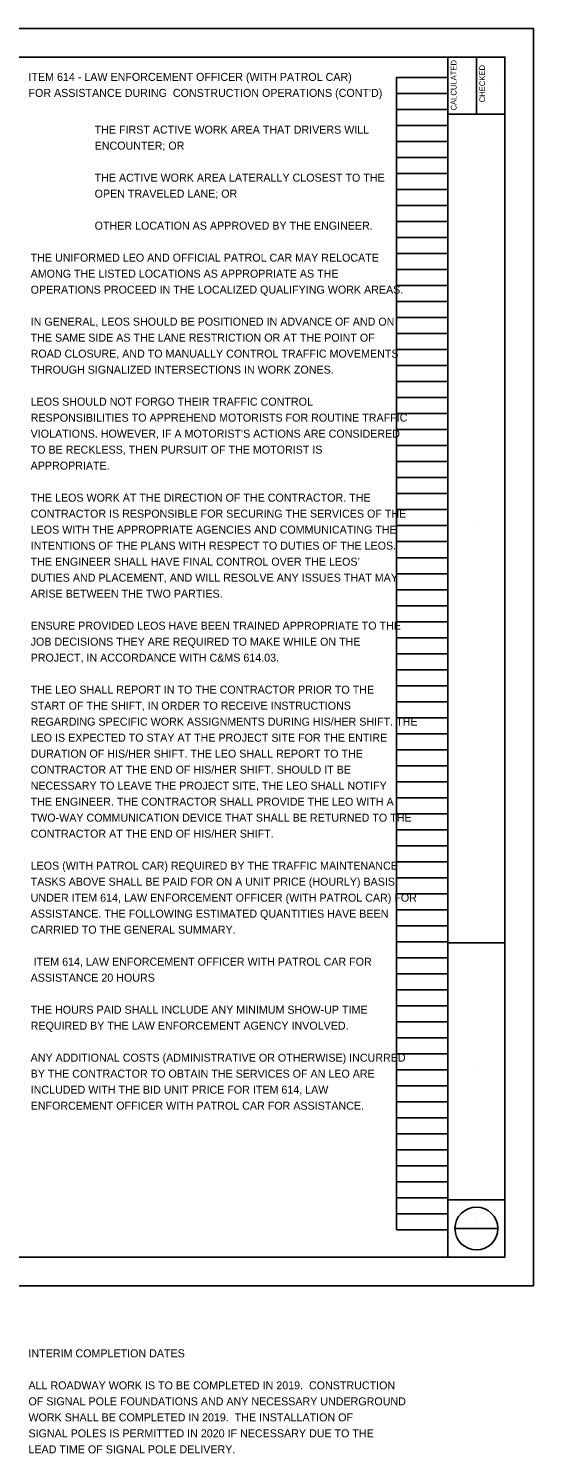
# Model space of a CAD drawing. Extents: x -10.9 to 54.4, y -2.9 to 34.3.
# Drawn here: x 25.16 to 34, y -2.94 to 22 of the extents above; entities that cross this region are included whole.
import ezdxf

# ---------------------------------------------------------------- set-up
doc = ezdxf.new("R2010")
doc.units = 0
for name, color, linetype in [('MT_P_Work_Area', 7, 'Continuous'), ('SH_Cut_Line', 7, 'Continuous'), ('SH_Data', 7, 'Continuous'), ('SH_Text', 7, 'Continuous')]:
    doc.layers.add(name, color=color, linetype=linetype)

msp = doc.modelspace()

# ---------------------------------------------------------------- linework, layer by layer
at = {"layer": 'MT_P_Work_Area'}
for p, q in [((32.5, 0.5), (32.5, 21.5)), ((33, 21.5), (33, 20.5)), ((32.5, 20.5), (33.5, 20.5)), ((32.5, 6), (33.5, 6)), ((32.5, 1.5), (33.5, 1.5))]:
    msp.add_line(p, q, dxfattribs=at)
msp.add_lwpolyline([(2, 21.5), (33.5, 21.5), (33.5, 0.5), (2, 0.5)], close=True, dxfattribs=at)
at = {"layer": 'SH_Cut_Line'}
msp.add_lwpolyline([(0, 0), (34, 0), (34, 22), (0, 22)], close=True, dxfattribs=at)
at = {"layer": 'SH_Data'}
for p, q in [((31.6, 0.98), (31.6, 21.14)), ((31.6, 21.14), (32.5, 21.14)), ((32.5, 0.98), (32.5, 21.14)), ((32.92, 21.004), (32.92, 21.004)), ((33.42, 21.004), (33.42, 21.004)), ((31.6, 20.86), (32.5, 20.86)), ((31.6, 20.58), (32.5, 20.58)), ((31.6, 20.3), (32.5, 20.3)), ((31.6, 20.02), (32.5, 20.02)), ((31.6, 19.74), (32.5, 19.74)), ((31.6, 19.46), (32.5, 19.46)), ((31.6, 19.18), (32.5, 19.18)), ((31.6, 18.9), (32.5, 18.9)), ((31.6, 18.62), (32.5, 18.62)), ((31.6, 18.34), (32.5, 18.34)), ((31.6, 18.06), (32.5, 18.06)), ((31.6, 17.78), (32.5, 17.78)), ((31.6, 17.5), (32.5, 17.5)), ((31.6, 17.22), (32.5, 17.22)), ((31.6, 16.94), (32.5, 16.94)), ((31.6, 16.66), (32.5, 16.66)), ((31.6, 16.38), (32.5, 16.38)), ((31.6, 16.1), (32.5, 16.1)), ((31.6, 15.82), (32.5, 15.82)), ((31.6, 15.54), (32.5, 15.54)), ((31.6, 15.26), (32.5, 15.26)), ((31.6, 14.98), (32.5, 14.98)), ((31.6, 14.7), (32.5, 14.7)), ((31.6, 14.42), (32.5, 14.42)), ((31.6, 14.14), (32.5, 14.14)), ((31.6, 13.86), (32.5, 13.86)), ((31.6, 13.58), (32.5, 13.58)), ((31.6, 13.3), (32.5, 13.3)), ((33, 13.292), (33, 13.292)), ((31.6, 13.02), (32.5, 13.02)), ((31.6, 12.74), (32.5, 12.74)), ((31.6, 12.46), (32.5, 12.46)), ((31.6, 12.18), (32.5, 12.18)), ((31.6, 11.9), (32.5, 11.9)), ((31.6, 11.62), (32.5, 11.62)), ((31.6, 11.34), (32.5, 11.34)), ((31.6, 11.06), (32.5, 11.06)), ((31.6, 10.78), (32.5, 10.78)), ((31.6, 10.5), (32.5, 10.5)), ((31.6, 10.22), (32.5, 10.22)), ((31.6, 9.94), (32.5, 9.94)), ((31.6, 9.66), (32.5, 9.66)), ((31.6, 9.38), (32.5, 9.38)), ((31.6, 9.1), (32.5, 9.1)), ((31.6, 8.82), (32.5, 8.82)), ((31.6, 8.54), (32.5, 8.54)), ((31.6, 8.26), (32.5, 8.26)), ((31.6, 7.98), (32.5, 7.98)), ((31.6, 7.7), (32.5, 7.7)), ((31.6, 7.42), (32.5, 7.42)), ((31.6, 7.14), (32.5, 7.14)), ((31.6, 6.86), (32.5, 6.86)), ((31.6, 6.58), (32.5, 6.58)), ((31.6, 6.3), (32.5, 6.3)), ((31.6, 6.02), (32.5, 6.02)), ((31.6, 5.74), (32.5, 5.74)), ((31.6, 5.46), (32.5, 5.46)), ((31.6, 5.18), (32.5, 5.18)), ((31.6, 4.9), (32.5, 4.9)), ((31.6, 4.62), (32.5, 4.62)), ((31.6, 4.34), (32.5, 4.34)), ((31.6, 4.06), (32.5, 4.06)), ((31.6, 3.78), (32.5, 3.78)), ((33, 3.792), (33, 3.792)), ((31.6, 3.5), (32.5, 3.5)), ((31.6, 3.22), (32.5, 3.22)), ((31.6, 2.94), (32.5, 2.94)), ((31.6, 2.66), (32.5, 2.66)), ((31.6, 2.38), (32.5, 2.38)), ((31.6, 2.1), (32.5, 2.1)), ((31.6, 1.82), (32.5, 1.82)), ((31.6, 1.54), (32.5, 1.54)), ((31.6, 1.26), (32.5, 1.26)), ((32.625, 1), (33.375, 1)), ((33, 1.085), (33, 1.085)), ((31.6, 0.98), (32.5, 0.98)), ((33, 0.745), (33, 0.745))]:
    msp.add_line(p, q, dxfattribs=at)
msp.add_circle((33, 1), 0.375, dxfattribs=at)

# ---------------------------------------------------------------- texts
for s, p in [('CALCULATED', (32.652, 20.565)), ('CHECKED', (33.152, 20.708))]:
    msp.add_text(s, height=0.1, rotation=90, dxfattribs=at).set_placement(p)
at = {"layer": 'SH_Text'}
for s, p in [('ITEM 614 - LAW ENFORCEMENT OFFICER (WITH PATROL CAR)', (25.16, 21.083)), ("FOR ASSISTANCE DURING  CONSTRUCTION OPERATIONS (CONT'D)", (25.16, 20.803)), ('THE FIRST ACTIVE WORK AREA THAT DRIVERS WILL ', (26.318, 20.16)), ('ENCOUNTER; OR', (26.318, 19.88)), ('THE ACTIVE WORK AREA LATERALLY CLOSEST TO THE ', (26.318, 19.32)), ('OPEN TRAVELED LANE; OR', (26.318, 19.04)), ('OTHER LOCATION AS APPROVED BY THE ENGINEER.', (26.318, 18.48)), ('THE UNIFORMED LEO AND OFFICIAL PATROL CAR MAY RELOCATE ', (25.198, 17.92)), ('AMONG THE LISTED LOCATIONS AS APPROPRIATE AS THE ', (25.198, 17.64)), ('OPERATIONS PROCEED IN THE LOCALIZED QUALIFYING WORK AREAS.', (25.198, 17.36)), ('IN GENERAL, LEOS SHOULD BE POSITIONED IN ADVANCE OF AND ON ', (25.198, 16.8)), ('THE SAME SIDE AS THE LANE RESTRICTION OR AT THE POINT OF ', (25.198, 16.52)), ('ROAD CLOSURE, AND TO MANUALLY CONTROL TRAFFIC MOVEMENTS ', (25.198, 16.24)), ('THROUGH SIGNALIZED INTERSECTIONS IN WORK ZONES. ', (25.198, 15.96)), ('LEOS SHOULD NOT FORGO THEIR TRAFFIC CONTROL ', (25.198, 15.4)), ('RESPONSIBILITIES TO APPREHEND MOTORISTS FOR ROUTINE TRAFFIC ', (25.198, 15.12)), ("VIOLATIONS. HOWEVER, IF A MOTORIST'S ACTIONS ARE CONSIDERED ", (25.198, 14.84)), ('TO BE RECKLESS, THEN PURSUIT OF THE MOTORIST IS ', (25.198, 14.56)), ('APPROPRIATE. ', (25.198, 14.28)), ('THE LEOS WORK AT THE DIRECTION OF THE CONTRACTOR. THE ', (25.198, 13.72)), ('CONTRACTOR IS RESPONSIBLE FOR SECURING THE SERVICES OF THE ', (25.198, 13.44)), ('LEOS WITH THE APPROPRIATE AGENCIES AND COMMUNICATING THE ', (25.198, 13.16)), ('INTENTIONS OF THE PLANS WITH RESPECT TO DUTIES OF THE LEOS. ', (25.198, 12.88)), ('THE ENGINEER SHALL HAVE FINAL CONTROL OVER THE LEOS’ ', (25.198, 12.6)), ('DUTIES AND PLACEMENT, AND WILL RESOLVE ANY ISSUES THAT MAY ', (25.198, 12.32)), ('ARISE BETWEEN THE TWO PARTIES. ', (25.198, 12.04)), ('ENSURE PROVIDED LEOS HAVE BEEN TRAINED APPROPRIATE TO THE ', (25.198, 11.48)), ('JOB DECISIONS THEY ARE REQUIRED TO MAKE WHILE ON THE ', (25.198, 11.2)), ('PROJECT, IN ACCORDANCE WITH C&MS 614.03. ', (25.198, 10.92)), ('THE LEO SHALL REPORT IN TO THE CONTRACTOR PRIOR TO THE ', (25.198, 10.36)), ('START OF THE SHIFT, IN ORDER TO RECEIVE INSTRUCTIONS ', (25.198, 10.08)), ('REGARDING SPECIFIC WORK ASSIGNMENTS DURING HIS/HER SHIFT. THE ', (25.198, 9.8)), ('LEO IS EXPECTED TO STAY AT THE PROJECT SITE FOR THE ENTIRE ', (25.198, 9.52)), ('DURATION OF HIS/HER SHIFT. THE LEO SHALL REPORT TO THE ', (25.198, 9.24)), ('CONTRACTOR AT THE END OF HIS/HER SHIFT. SHOULD IT BE ', (25.198, 8.96)), ('NECESSARY TO LEAVE THE PROJECT SITE, THE LEO SHALL NOTIFY ', (25.198, 8.68)), ('THE ENGINEER. THE CONTRACTOR SHALL PROVIDE THE LEO WITH A ', (25.198, 8.4)), ('TWO-WAY COMMUNICATION DEVICE THAT SHALL BE RETURNED TO THE ', (25.198, 8.12)), ('CONTRACTOR AT THE END OF HIS/HER SHIFT.', (25.198, 7.84)), ('LEOS (WITH PATROL CAR) REQUIRED BY THE TRAFFIC MAINTENANCE ', (25.198, 7.28)), ('TASKS ABOVE SHALL BE PAID FOR ON A UNIT PRICE (HOURLY) BASIS ', (25.198, 7)), ('UNDER ITEM 614, LAW ENFORCEMENT OFFICER (WITH PATROL CAR) FOR ', (25.198, 6.72)), ('ASSISTANCE. THE FOLLOWING ESTIMATED QUANTITIES HAVE BEEN ', (25.198, 6.44)), ('CARRIED TO THE GENERAL SUMMARY.', (25.198, 6.16)), (' ITEM 614, LAW ENFORCEMENT OFFICER WITH PATROL CAR FOR ', (25.198, 5.6)), ('ASSISTANCE 20 HOURS ', (25.198, 5.32)), ('THE HOURS PAID SHALL INCLUDE ANY MINIMUM SHOW-UP TIME ', (25.198, 4.76)), ('REQUIRED BY THE LAW ENFORCEMENT AGENCY INVOLVED. ', (25.198, 4.48)), ('ANY ADDITIONAL COSTS (ADMINISTRATIVE OR OTHERWISE) INCURRED ', (25.198, 3.92)), ('BY THE CONTRACTOR TO OBTAIN THE SERVICES OF AN LEO ARE ', (25.198, 3.64)), ('INCLUDED WITH THE BID UNIT PRICE FOR ITEM 614, LAW ', (25.198, 3.36)), ('ENFORCEMENT OFFICER WITH PATROL CAR FOR ASSISTANCE.', (25.198, 3.08)), ('INTERIM COMPLETION DATES', (25.16, -1.254)), ('ALL ROADWAY WORK IS TO BE COMPLETED IN 2019.  CONSTRUCTION', (25.16, -1.814)), ('OF SIGNAL POLE FOUNDATIONS AND ANY NECESSARY UNDERGROUND', (25.16, -2.094)), ('WORK SHALL BE COMPLETED IN 2019.  THE INSTALLATION OF', (25.16, -2.374)), ('SIGNAL POLES IS PERMITTED IN 2020 IF NECESSARY DUE TO THE', (25.16, -2.654)), ('LEAD TIME OF SIGNAL POLE DELIVERY.', (25.16, -2.934))]:
    msp.add_text(s, height=0.14, dxfattribs=at).set_placement(p)

doc.saveas('drawing.dxf')
